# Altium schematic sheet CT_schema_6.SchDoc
size 251 x 159 mm
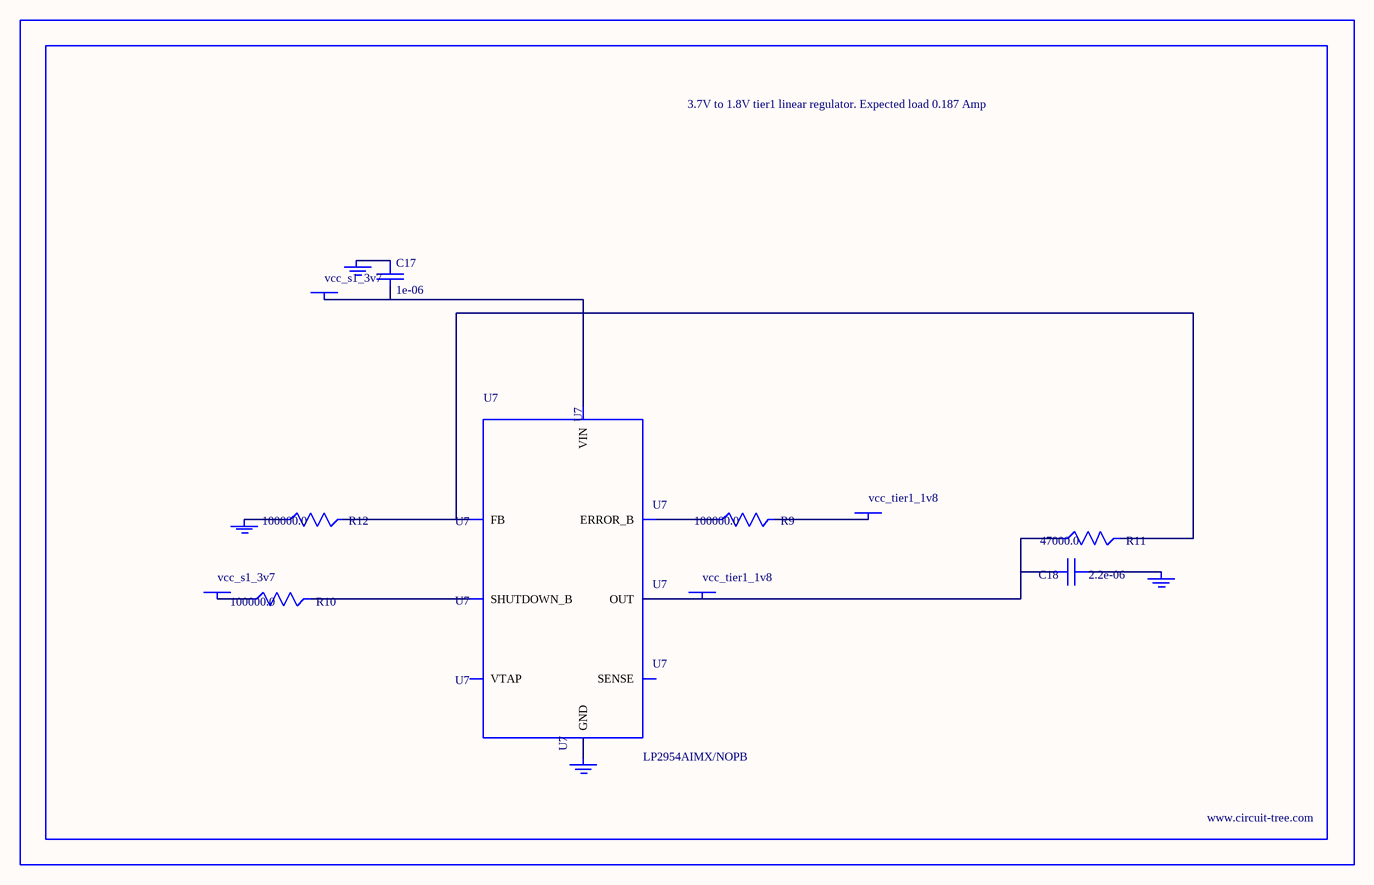
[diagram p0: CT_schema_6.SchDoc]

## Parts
BORDER5  (no value)
C17  1e-06  [EXV-9B]
C18  2.2e-06  [EXV-9B]
GND_INSTANCE_5_0  (no value)
GND_INSTANCE_5_1  (no value)
GND_INSTANCE_5_2  (no value)
GND_INSTANCE_5_3  (no value)
POWER_INSTANCE_5_0  vcc_s1_3v7
POWER_INSTANCE_5_1  vcc_tier1_1v8
POWER_INSTANCE_5_2  vcc_s1_3v7
POWER_INSTANCE_5_3  vcc_tier1_1v8
R9  100000.0  [R0603]
R10  100000.0  [R0603]
R11  47000.0  [R0603]
R12  100000.0  [R0603]
U7  LP2954AIMX/NOPB  [LP2954]

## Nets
NetC17_1: C17.1 GND_INSTANCE_5_2.0(GND)
NetC17_2: C17.2 POWER_INSTANCE_5_2.0(PWR) U7.8(VIN)
NetC18_1: C18.1 GND_INSTANCE_5_0.0(GND)
NetC18_2: C18.2 POWER_INSTANCE_5_3.0(PWR) R11.1 U7.1(OUT)
NetGND_INSTANCE_5_1_0: GND_INSTANCE_5_1.0(GND) R12.1
NetGND_INSTANCE_5_3_0: GND_INSTANCE_5_3.0(GND) U7.4(GND)
NetPOWER_INSTANCE_5_0_0: POWER_INSTANCE_5_0.0(PWR) R10.1
NetPOWER_INSTANCE_5_1_0: POWER_INSTANCE_5_1.0(PWR) R9.2
NetR9_1: R9.1 U7.5(ERROR_B)
NetR10_2: R10.2 U7.3(SHUTDOWN_B)
NetR11_2: R11.2 R12.2 U7.7(FB)

Not connected (* = marked no-connect by the designer): U7 2(SENSE) 6(VTAP)

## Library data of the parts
BORDER5 = BORDER_PAGE5
C17 = EDK105M050A9BAA
C18 = EDK225M050A9BAA
GND_INSTANCE_5_0-GND_INSTANCE_5_3 = GND
POWER_INSTANCE_5_0-POWER_INSTANCE_5_3 = PWR
R9 R10 R12 = RC0603JR-07100KL
R11 = RC0603JR-0747KL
